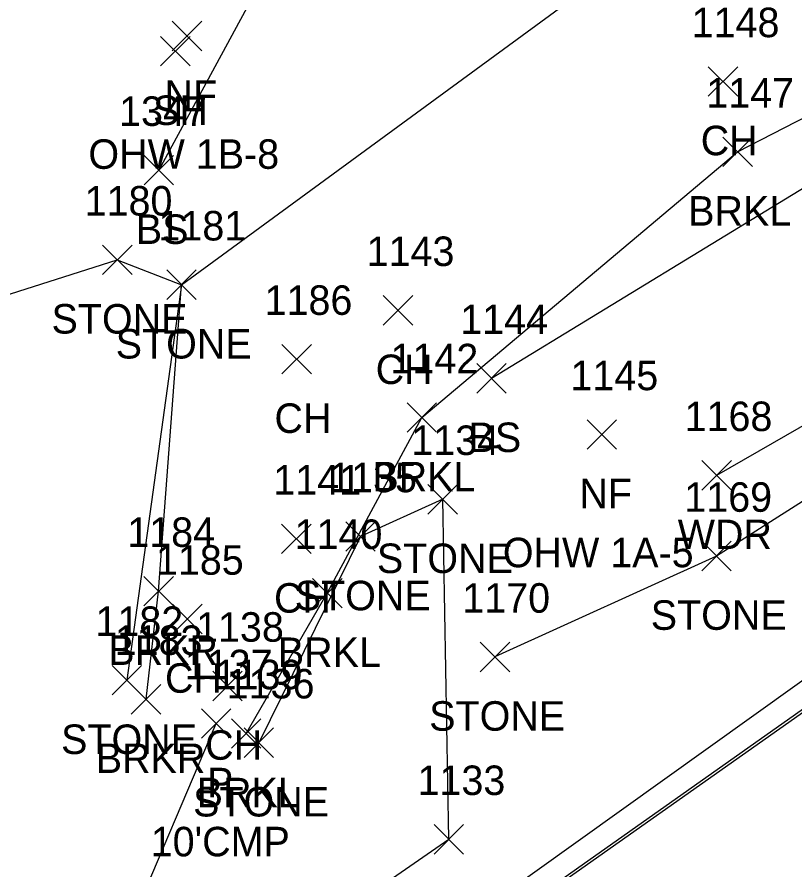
# Model space of a CAD drawing. Extents: x 1528286 to 1556263, y 492387 to 508952.
# Drawn here: x 1528684.2 to 1528736.9, y 492849.7 to 492907.5 of the extents above; entities that cross this region are included whole.
import ezdxf

# ---------------------------------------------------------------- set-up
doc = ezdxf.new("R2010")
doc.units = 0
for name, color, linetype in [('D_A', 7, 'Continuous'), ('D_C', 7, 'Continuous'), ('D_I', 7, 'Continuous'), ('D_TIC', 7, 'Continuous'), ('DCP', 7, 'Continuous'), ('L_A', 7, 'Continuous'), ('L_C', 7, 'Continuous'), ('L_I', 7, 'Continuous'), ('L_TIC', 7, 'Continuous'), ('LASF', 7, 'Continuous'), ('LAWA', 7, 'Continuous'), ('LAWE', 7, 'Continuous'), ('LELB', 7, 'Continuous'), ('PET', 7, 'Continuous'), ('RGR', 7, 'Continuous')]:
    doc.layers.add(name, color=color, linetype=linetype)

msp = doc.modelspace()

# ---------------------------------------------------------------- linework, layer by layer
at = {"layer": 'D_TIC'}
for points in [[(1528696.661, 492858.59), (1528698.661, 492860.59)], [(1528698.661, 492858.59), (1528696.661, 492860.59)], [(1528696.661, 492858.59), (1528698.661, 492860.59)], [(1528698.661, 492858.59), (1528696.661, 492860.59)]]:
    msp.add_lwpolyline(points, dxfattribs=at)
at = {"layer": 'DCP'}
msp.add_lwpolyline([(1528644.198, 492733.843), (1528697.661, 492859.59)], dxfattribs=at)
msp.add_lwpolyline([(1528644.198, 492733.843), (1528697.661, 492859.59)], dxfattribs=at)
at = {"layer": 'L_TIC'}
for points in [[(1528694.682, 492905.187), (1528696.682, 492907.187)], [(1528696.682, 492905.187), (1528694.682, 492907.187)], [(1528694.682, 492905.187), (1528696.682, 492907.187)], [(1528696.682, 492905.187), (1528694.682, 492907.187)], [(1528693.896, 492904.158), (1528695.896, 492906.158)], [(1528695.896, 492904.158), (1528693.896, 492906.158)], [(1528693.896, 492904.158), (1528695.896, 492906.158)], [(1528695.896, 492904.158), (1528693.896, 492906.158)], [(1528731.015, 492902.109), (1528733.015, 492904.109)], [(1528733.015, 492902.109), (1528731.015, 492904.109)], [(1528731.015, 492902.109), (1528733.015, 492904.109)], [(1528733.015, 492902.109), (1528731.015, 492904.109)], [(1528732.006, 492897.336), (1528734.006, 492899.336)], [(1528734.006, 492897.336), (1528732.006, 492899.336)], [(1528732.006, 492897.336), (1528734.006, 492899.336)], [(1528734.006, 492897.336), (1528732.006, 492899.336)], [(1528692.777, 492896.095), (1528694.777, 492898.095)], [(1528694.777, 492896.095), (1528692.777, 492898.095)], [(1528692.777, 492896.095), (1528694.777, 492898.095)], [(1528694.777, 492896.095), (1528692.777, 492898.095)], [(1528689.962, 492890.022), (1528691.962, 492892.022)], [(1528691.962, 492890.022), (1528689.962, 492892.022)], [(1528689.962, 492890.022), (1528691.962, 492892.022)], [(1528691.962, 492890.022), (1528689.962, 492892.022)], [(1528694.312, 492888.331), (1528696.312, 492890.331)], [(1528696.312, 492888.331), (1528694.312, 492890.331)], [(1528694.312, 492888.331), (1528696.312, 492890.331)], [(1528696.312, 492888.331), (1528694.312, 492890.331)], [(1528708.985, 492886.599), (1528710.985, 492888.599)], [(1528710.985, 492886.599), (1528708.985, 492888.599)], [(1528708.985, 492886.599), (1528710.985, 492888.599)], [(1528710.985, 492886.599), (1528708.985, 492888.599)], [(1528702.125, 492883.288), (1528704.125, 492885.288)], [(1528704.125, 492883.288), (1528702.125, 492885.288)], [(1528702.125, 492883.288), (1528704.125, 492885.288)], [(1528704.125, 492883.288), (1528702.125, 492885.288)], [(1528715.329, 492881.991), (1528717.329, 492883.991)], [(1528717.329, 492881.991), (1528715.329, 492883.991)], [(1528715.329, 492881.991), (1528717.329, 492883.991)], [(1528717.329, 492881.991), (1528715.329, 492883.991)], [(1528710.604, 492879.328), (1528712.604, 492881.328)], [(1528712.604, 492879.328), (1528710.604, 492881.328)], [(1528710.604, 492879.328), (1528712.604, 492881.328)], [(1528712.604, 492879.328), (1528710.604, 492881.328)], [(1528722.801, 492878.184), (1528724.801, 492880.184)], [(1528724.801, 492878.184), (1528722.801, 492880.184)], [(1528722.801, 492878.184), (1528724.801, 492880.184)], [(1528724.801, 492878.184), (1528722.801, 492880.184)], [(1528730.583, 492875.413), (1528732.583, 492877.413)], [(1528732.583, 492875.413), (1528730.583, 492877.413)], [(1528730.583, 492875.413), (1528732.583, 492877.413)], [(1528732.583, 492875.413), (1528730.583, 492877.413)], [(1528712.016, 492873.791), (1528714.016, 492875.791)], [(1528714.016, 492873.791), (1528712.016, 492875.791)], [(1528712.016, 492873.791), (1528714.016, 492875.791)], [(1528714.016, 492873.791), (1528712.016, 492875.791)], [(1528702.096, 492871.107), (1528704.096, 492873.107)], [(1528704.096, 492871.107), (1528702.096, 492873.107)], [(1528702.096, 492871.107), (1528704.096, 492873.107)], [(1528704.096, 492871.107), (1528702.096, 492873.107)], [(1528706.447, 492871.268), (1528708.447, 492873.268)], [(1528708.447, 492871.268), (1528706.447, 492873.268)], [(1528706.447, 492871.268), (1528708.447, 492873.268)], [(1528708.447, 492871.268), (1528706.447, 492873.268)], [(1528730.574, 492869.943), (1528732.574, 492871.943)], [(1528732.574, 492869.943), (1528730.574, 492871.943)], [(1528730.574, 492869.943), (1528732.574, 492871.943)], [(1528732.574, 492869.943), (1528730.574, 492871.943)], [(1528692.762, 492867.562), (1528694.762, 492869.562)], [(1528694.762, 492867.562), (1528692.762, 492869.562)], [(1528692.762, 492867.562), (1528694.762, 492869.562)], [(1528694.762, 492867.562), (1528692.762, 492869.562)], [(1528704.195, 492867.423), (1528706.195, 492869.423)], [(1528706.195, 492867.423), (1528704.195, 492869.423)], [(1528704.195, 492867.423), (1528706.195, 492869.423)], [(1528706.195, 492867.423), (1528704.195, 492869.423)], [(1528694.706, 492865.677), (1528696.706, 492867.677)], [(1528696.706, 492865.677), (1528694.706, 492867.677)], [(1528694.706, 492865.677), (1528696.706, 492867.677)], [(1528696.706, 492865.677), (1528694.706, 492867.677)], [(1528715.559, 492863.104), (1528717.559, 492865.104)], [(1528717.559, 492863.104), (1528715.559, 492865.104)], [(1528715.559, 492863.104), (1528717.559, 492865.104)], [(1528717.559, 492863.104), (1528715.559, 492865.104)], [(1528690.609, 492861.526), (1528692.609, 492863.526)], [(1528692.609, 492861.526), (1528690.609, 492863.526)], [(1528690.609, 492861.526), (1528692.609, 492863.526)], [(1528692.609, 492861.526), (1528690.609, 492863.526)], [(1528697.428, 492861.136), (1528699.428, 492863.136)], [(1528699.428, 492861.136), (1528697.428, 492863.136)], [(1528697.428, 492861.136), (1528699.428, 492863.136)], [(1528699.428, 492861.136), (1528697.428, 492863.136)], [(1528691.913, 492860.237), (1528693.913, 492862.237)], [(1528693.913, 492860.237), (1528691.913, 492862.237)], [(1528691.913, 492860.237), (1528693.913, 492862.237)], [(1528693.913, 492860.237), (1528691.913, 492862.237)], [(1528698.698, 492857.914), (1528700.698, 492859.914)], [(1528700.698, 492857.914), (1528698.698, 492859.914)], [(1528698.698, 492857.914), (1528700.698, 492859.914)], [(1528700.698, 492857.914), (1528698.698, 492859.914)], [(1528699.556, 492857.291), (1528701.556, 492859.291)], [(1528701.556, 492857.291), (1528699.556, 492859.291)], [(1528699.556, 492857.291), (1528701.556, 492859.291)], [(1528701.556, 492857.291), (1528699.556, 492859.291)], [(1528712.436, 492850.745), (1528714.436, 492852.745)], [(1528714.436, 492850.745), (1528712.436, 492852.745)], [(1528712.436, 492850.745), (1528714.436, 492852.745)], [(1528714.436, 492850.745), (1528712.436, 492852.745)]]:
    msp.add_lwpolyline(points, dxfattribs=at)
at = {"layer": 'LASF'}
for points in [[(1528803.204, 492913.579), (1528764.365, 492891.78), (1528731.574, 492870.943), (1528716.559, 492864.104)], [(1528803.204, 492913.579), (1528764.365, 492891.78), (1528731.574, 492870.943), (1528716.559, 492864.104)], [(1528672.244, 492851.139), (1528675.29, 492858.204), (1528679.101, 492887.236), (1528690.962, 492891.022), (1528695.312, 492889.331), (1528691.609, 492862.526)], [(1528672.244, 492851.139), (1528675.29, 492858.204), (1528679.101, 492887.236), (1528690.962, 492891.022), (1528695.312, 492889.331), (1528691.609, 492862.526)], [(1528697.435, 492840.692), (1528713.436, 492851.745), (1528713.016, 492874.791), (1528707.447, 492872.268), (1528700.556, 492858.291)], [(1528697.435, 492840.692), (1528713.436, 492851.745), (1528713.016, 492874.791), (1528707.447, 492872.268), (1528700.556, 492858.291)]]:
    msp.add_lwpolyline(points, dxfattribs=at)
at = {"layer": 'LAWA'}
msp.add_lwpolyline([(1528932.821, 493004.859), (1528877.302, 492973.439), (1528838.449, 492947.788), (1528805.62, 492925.402), (1528761.436, 492893.561), (1528731.583, 492876.413)], dxfattribs=at)
msp.add_lwpolyline([(1528932.821, 493004.859), (1528877.302, 492973.439), (1528838.449, 492947.788), (1528805.62, 492925.402), (1528761.436, 492893.561), (1528731.583, 492876.413)], dxfattribs=at)
at = {"layer": 'LAWE'}
for points in [[(1528699.698, 492858.914), (1528705.195, 492868.423), (1528711.604, 492880.328), (1528733.006, 492898.336), (1528756.206, 492910.282), (1528789.072, 492931.124), (1528812.92, 492945.763), (1528839.473, 492958.791)], [(1528699.698, 492858.914), (1528705.195, 492868.423), (1528711.604, 492880.328), (1528733.006, 492898.336), (1528756.206, 492910.282), (1528789.072, 492931.124), (1528812.92, 492945.763), (1528839.473, 492958.791)], [(1528693.762, 492868.562), (1528695.312, 492889.331), (1528746.807, 492927.028)], [(1528692.913, 492861.237), (1528693.762, 492868.562)], [(1528692.913, 492861.237), (1528693.762, 492868.562)]]:
    msp.add_lwpolyline(points, dxfattribs=at)
at = {"layer": 'LELB'}
for points in [[(1528511.531, 492702.846), (1528534.14, 492721.314), (1528572.642, 492751.164), (1528586.729, 492763.586), (1528600.497, 492766.346), (1528613.458, 492775.516), (1528652.2, 492802.526), (1528688.619, 492828.262), (1528710.289, 492843.118), (1528742.907, 492866.471), (1528778.713, 492891.266), (1528817.445, 492919.082), (1528857.746, 492946.937), (1528897.372, 492973.983), (1528940.286, 493003.739)], [(1528511.531, 492702.846), (1528534.14, 492721.314), (1528572.642, 492751.164), (1528586.729, 492763.586), (1528600.497, 492766.346), (1528613.458, 492775.516), (1528652.2, 492802.526), (1528688.619, 492828.262), (1528710.289, 492843.118), (1528742.907, 492866.471), (1528778.713, 492891.266), (1528817.445, 492919.082), (1528857.746, 492946.937), (1528897.372, 492973.983), (1528940.286, 493003.739)], [(1528641.693, 492985.749), (1528687.133, 492952.057), (1528713.307, 492933.14), (1528693.777, 492897.095)], [(1528641.693, 492985.749), (1528687.133, 492952.057), (1528713.307, 492933.14), (1528693.777, 492897.095)], [(1528716.329, 492882.991), (1528739.424, 492897.091), (1528757.723, 492908.665), (1528787.402, 492928.88), (1528815.352, 492943.517), (1528839.473, 492958.791)], [(1528716.329, 492882.991), (1528739.424, 492897.091), (1528757.723, 492908.665), (1528787.402, 492928.88), (1528815.352, 492943.517), (1528839.473, 492958.791)]]:
    msp.add_lwpolyline(points, dxfattribs=at)
at = {"layer": 'PET'}
msp.add_lwpolyline([(1528941.998, 493002.12), (1528898.48, 492972.509), (1528859.279, 492945.341), (1528819.079, 492917.533), (1528787.553, 492894.483), (1528780.465, 492889.936), (1528744.229, 492865.118), (1528711.173, 492841.816), (1528689.558, 492826.658), (1528653.332, 492801.515)], dxfattribs=at)
msp.add_lwpolyline([(1528941.998, 493002.12), (1528898.48, 492972.509), (1528859.279, 492945.341), (1528819.079, 492917.533), (1528787.553, 492894.483), (1528780.465, 492889.936), (1528744.229, 492865.118), (1528711.173, 492841.816), (1528689.558, 492826.658), (1528653.332, 492801.515)], dxfattribs=at)
at = {"layer": 'RGR'}
msp.add_lwpolyline([(1528941.405, 493002.785), (1528898.116, 492973.218), (1528858.975, 492945.897), (1528818.829, 492918.12), (1528780.054, 492890.637), (1528744.146, 492865.314), (1528711.237, 492842.066), (1528689.599, 492826.87), (1528653.301, 492801.623)], dxfattribs=at)
msp.add_lwpolyline([(1528941.405, 493002.785), (1528898.116, 492973.218), (1528858.975, 492945.897), (1528818.829, 492918.12), (1528780.054, 492890.637), (1528744.146, 492865.314), (1528711.237, 492842.066), (1528689.599, 492826.87), (1528653.301, 492801.623)], dxfattribs=at)

# ---------------------------------------------------------------- texts
at = {"layer": 'D_A'}
msp.add_text('P', height=2, dxfattribs=at).set_placement((1528697.039, 492854.59))
msp.add_text('P', height=2, dxfattribs=at).set_placement((1528697.039, 492854.59))
at = {"layer": 'D_C'}
msp.add_text("10'CMP", height=2, dxfattribs=at).set_placement((1528693.228, 492850.59))
msp.add_text("10'CMP", height=2, dxfattribs=at).set_placement((1528693.228, 492850.59))
at = {"layer": 'D_I'}
msp.add_text('1137', height=2, dxfattribs=at).set_placement((1528695.535, 492862.59))
msp.add_text('1137', height=2, dxfattribs=at).set_placement((1528695.535, 492862.59))
at = {"layer": 'L_A'}
for s, p in [('NF', (1528694.162, 492901.187)), ('NF', (1528694.162, 492901.187)), ('SH', (1528693.385, 492900.158)), ('SH', (1528693.385, 492900.158)), ('CH', (1528730.503, 492898.109)), ('CH', (1528730.503, 492898.109)), ('BRKL', (1528729.652, 492893.336)), ('BRKL', (1528729.652, 492893.336)), ('BS', (1528692.218, 492892.095)), ('BS', (1528692.218, 492892.095)), ('STONE', (1528686.506, 492886.022)), ('STONE', (1528686.506, 492886.022)), ('STONE', (1528690.855, 492884.331)), ('STONE', (1528690.855, 492884.331)), ('CH', (1528708.473, 492882.599)), ('CH', (1528708.473, 492882.599)), ('CH', (1528701.613, 492879.288)), ('CH', (1528701.613, 492879.288)), ('BS', (1528714.77, 492877.991)), ('BS', (1528714.77, 492877.991)), ('BRKL', (1528708.25, 492875.328)), ('BRKL', (1528708.25, 492875.328)), ('NF', (1528722.281, 492874.184)), ('NF', (1528722.281, 492874.184)), ('WDR', (1528728.945, 492871.413)), ('WDR', (1528728.945, 492871.413)), ('STONE', (1528708.559, 492869.791)), ('STONE', (1528708.559, 492869.791)), ('CH', (1528701.584, 492867.107)), ('CH', (1528701.584, 492867.107)), ('STONE', (1528702.99, 492867.268)), ('STONE', (1528702.99, 492867.268)), ('STONE', (1528727.117, 492865.943)), ('STONE', (1528727.117, 492865.943)), ('BRKR', (1528690.352, 492863.562)), ('BRKR', (1528690.352, 492863.562)), ('BRKL', (1528701.84, 492863.423)), ('BRKL', (1528701.84, 492863.423)), ('CH', (1528694.194, 492861.677)), ('CH', (1528694.194, 492861.677)), ('STONE', (1528712.102, 492859.104)), ('STONE', (1528712.102, 492859.104)), ('STONE', (1528687.153, 492857.526)), ('STONE', (1528687.153, 492857.526)), ('CH', (1528696.916, 492857.136)), ('CH', (1528696.916, 492857.136)), ('BRKR', (1528689.503, 492856.237)), ('BRKR', (1528689.503, 492856.237)), ('BRKL', (1528696.344, 492853.914)), ('BRKL', (1528696.344, 492853.914)), ('STONE', (1528696.099, 492853.291)), ('STONE', (1528696.099, 492853.291))]:
    msp.add_text(s, height=2, dxfattribs=at).set_placement(p)
at = {"layer": 'L_C'}
for s, p in [('OHW 1B-8', (1528689.004, 492897.187)), ('OHW 1B-8', (1528689.004, 492897.187)), ('OHW 1A-5', (1528717.092, 492870.184)), ('OHW 1A-5', (1528717.092, 492870.184))]:
    msp.add_text(s, height=2, dxfattribs=at).set_placement(p)
at = {"layer": 'L_I'}
for s, p in [('1148', (1528729.889, 492906.109)), ('1148', (1528729.889, 492906.109)), ('1147', (1528730.88, 492901.336)), ('1147', (1528730.88, 492901.336)), ('1347', (1528691.084, 492900.095)), ('1347', (1528691.084, 492900.095)), ('1180', (1528688.75, 492894.022)), ('1180', (1528688.75, 492894.022)), ('1181', (1528693.753, 492892.331)), ('1181', (1528693.753, 492892.331)), ('1143', (1528707.859, 492890.599)), ('1143', (1528707.859, 492890.599)), ('1186', (1528700.944, 492887.288)), ('1186', (1528700.944, 492887.288)), ('1144', (1528714.203, 492885.991)), ('1144', (1528714.203, 492885.991)), ('1142', (1528709.478, 492883.328)), ('1142', (1528709.478, 492883.328)), ('1145', (1528721.675, 492882.184)), ('1145', (1528721.675, 492882.184)), ('1168', (1528729.409, 492879.413)), ('1168', (1528729.409, 492879.413)), ('1134', (1528710.89, 492877.791)), ('1134', (1528710.89, 492877.791)), ('1141', (1528701.537, 492875.107)), ('1141', (1528701.537, 492875.107)), ('1135', (1528705.321, 492875.268)), ('1135', (1528705.321, 492875.268)), ('1169', (1528729.393, 492873.943)), ('1169', (1528729.393, 492873.943)), ('1184', (1528691.636, 492871.562)), ('1184', (1528691.636, 492871.562)), ('1140', (1528702.982, 492871.423)), ('1140', (1528702.982, 492871.423)), ('1185', (1528693.58, 492869.677)), ('1185', (1528693.58, 492869.677)), ('1170', (1528714.347, 492867.104)), ('1170', (1528714.347, 492867.104)), ('1182', (1528689.483, 492865.526)), ('1182', (1528689.483, 492865.526)), ('1138', (1528696.302, 492865.136)), ('1138', (1528696.302, 492865.136)), ('1183', (1528690.787, 492864.237)), ('1183', (1528690.787, 492864.237)), ('1139', (1528697.564, 492861.914)), ('1139', (1528697.564, 492861.914)), ('1136', (1528698.375, 492861.291)), ('1136', (1528698.375, 492861.291)), ('1133', (1528711.31, 492854.745)), ('1133', (1528711.31, 492854.745))]:
    msp.add_text(s, height=2, dxfattribs=at).set_placement(p)

doc.saveas('drawing.dxf')
